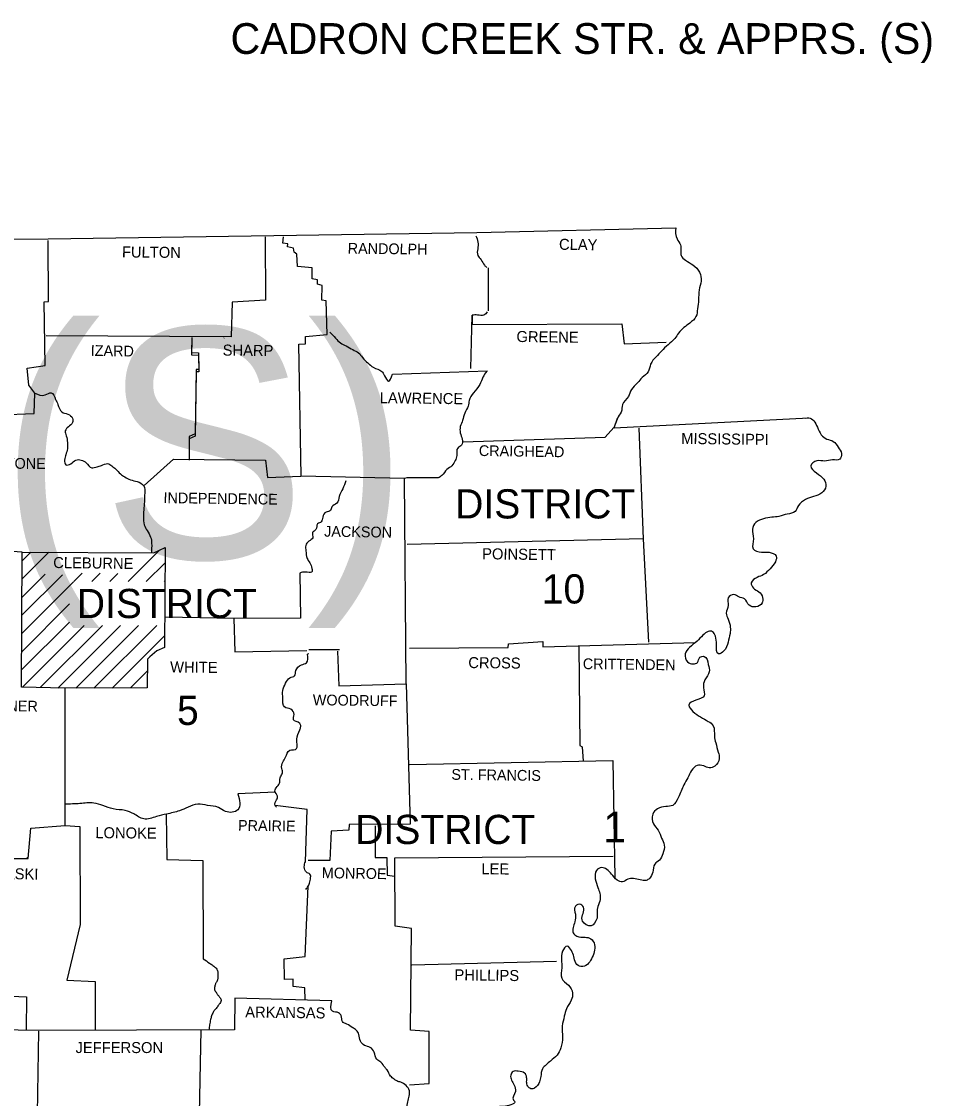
# Model space of a CAD drawing. Extents: x 1212896 to 1368412, y 378476 to 478763.
# Drawn here: x 1348211 to 1365971, y 454801 to 475822 of the extents above; entities that cross this region are included whole.
import ezdxf

# ---------------------------------------------------------------- set-up
doc = ezdxf.new("R2010")
doc.units = 0
doc.layers.add('1', color=7, linetype='Continuous')
doc.layers.add('R_Draft', color=7, linetype='Continuous')

msp = doc.modelspace()

# ---------------------------------------------------------------- linework, layer by layer
at = {"layer": 'R_Draft'}
for p, q in [((1359780, 467892), (1359840, 468077)), ((1359795, 467952), (1359855, 468097)), ((1348222, 464943), (1348743, 465464)), ((1348224, 465298), (1348391, 465466)), ((1350289, 464889), (1350904, 465504)), ((1350643, 464889), (1351012, 465259)), ((1348218, 464232), (1349010, 465024)), ((1348220, 464587), (1348670, 465037)), ((1349229, 464889), (1349397, 465057)), ((1349582, 464889), (1349744, 465051)), ((1349936, 464889), (1350093, 465046)), ((1348216, 463876), (1349227, 464888)), ((1350997, 464889), (1351010, 464902)), ((1348214, 463520), (1349147, 464454)), ((1348212, 463165), (1349147, 464100)), ((1348231, 462831), (1349434, 464034)), ((1348575, 462821), (1349788, 464034)), ((1348918, 462811), (1350142, 464034)), ((1349269, 462808), (1350495, 464034)), ((1349625, 462810), (1350849, 464034)), ((1349980, 462812), (1351002, 463833)), ((1353820, 463562), (1354415, 463562)), ((1350336, 462815), (1350668, 463146))]:
    msp.add_line(p, q, dxfattribs=at)
for points in [[(1333550, 471567), (1341635, 471562), (1348730, 471577), (1357100, 471707), (1360980, 471797)], [(1347215, 459482), (1348340, 459487), (1348390, 460077), (1349060, 460127), (1349060, 462807), (1348210, 462832), (1348225, 465467), (1347155, 465537), (1347140, 466717), (1347105, 466777), (1347135, 467517), (1347755, 467537), (1347780, 468147), (1348460, 468172), (1348470, 468567), (1348350, 468722), (1348320, 469057), (1348670, 469107), (1348655, 470352), (1348740, 470357), (1348730, 471547)], [(1352965, 471622), (1352975, 470382), (1352325, 470347), (1352305, 469667), (1348690, 469687)], [(1354380, 463532), (1354405, 462857), (1355720, 462892), (1355685, 466902), (1353670, 466947), (1353625, 469527), (1353755, 469532), (1353750, 469672), (1354175, 469712), (1354155, 470367), (1354075, 470382), (1354080, 470672), (1353990, 470697), (1353990, 470782), (1353885, 470797), (1353885, 471012), (1353600, 471042), (1353585, 471282), (1353530, 471317), (1353520, 471397), (1353405, 471422), (1353410, 471482), (1353310, 471497), (1353325, 471617)], [(1357320, 471017), (1357320, 470172)], [(1356980, 469047), (1357005, 470092), (1357005, 469907), (1359930, 469922), (1359970, 469532), (1360795, 469562)], [(1351535, 469652), (1351525, 469362), (1351665, 469352), (1351670, 469032), (1351620, 469032), (1351600, 467772), (1351485, 467722), (1351485, 467302)], [(1351535, 469607), (1351525, 469317), (1351665, 469307), (1351670, 468987), (1351620, 468987), (1351600, 467727), (1351485, 467677), (1351485, 467257)], [(1352160, 469642), (1352165, 469647)], [(1355450, 468937), (1357305, 469002)], [(1359780, 467892), (1363575, 468087)], [(1356830, 467617), (1359605, 467707), (1359770, 467897)], [(1360260, 467887), (1360345, 465722), (1360445, 463707)], [(1350605, 466767), (1351175, 467282), (1352975, 467257), (1353010, 466922), (1353665, 466947)], [(1356340, 466912), (1355730, 466912), (1355685, 466902)], [(1360345, 465722), (1355740, 465617)], [(1348225, 465467), (1350795, 465452), (1351015, 465557), (1351000, 463602), (1350850, 463537), (1350715, 463422), (1350670, 463377), (1350665, 462817), (1349060, 462807)], [(1353645, 465057), (1353655, 464177), (1352355, 464172), (1351020, 464197)], [(1352355, 464172), (1352375, 463517), (1353780, 463542)], [(1355780, 463592), (1357710, 463602), (1357715, 463672), (1358385, 463722), (1358385, 463617), (1361363, 463698)], [(1359085, 463636), (1359110, 461692), (1359155, 461662), (1359171, 461385)], [(1353820, 463477), (1353795, 463472)], [(1355720, 462892), (1355795, 460152), (1354605, 460147), (1354600, 460037), (1354255, 460017), (1354225, 459447), (1353805, 459447)], [(1355780, 461317), (1359750, 461397)], [(1359750, 461397), (1359792, 459106)], [(1353160, 460782), (1352435, 460747)], [(1353750, 459422), (1353785, 460442), (1353160, 460522)], [(1351035, 460350), (1351045, 459462), (1351750, 459447), (1351755, 457527)], [(1349060, 460127), (1349350, 460107), (1349355, 458197), (1349095, 457112), (1349650, 457087), (1349645, 456131)], [(1355115, 460122), (1355110, 459502), (1355340, 459502), (1355350, 459157), (1355495, 459142)], [(1348315, 459492), (1348340, 459517)], [(1355780, 455067), (1356170, 455092), (1356165, 456107), (1355800, 456132), (1355820, 458117), (1355505, 458162), (1355495, 459497), (1359760, 459527)], [(1353747, 456720), (1353740, 456962), (1353515, 456987), (1353510, 457127), (1353345, 457122), (1353335, 457527), (1353745, 457572), (1353805, 458942)], [(1345200, 458877), (1345760, 458842), (1345740, 458217), (1346395, 458192), (1346405, 457647), (1346715, 457622), (1346715, 457527), (1347005, 457507), (1347015, 457157), (1347675, 457157), (1347695, 456812), (1348305, 456782), (1348300, 456132)], [(1355830, 457412), (1358650, 457482)], [(1354265, 456707), (1352375, 456757), (1352365, 456142), (1348540, 456127)], [(1348540, 456127), (1347345, 456147), (1347300, 455842), (1346135, 455807), (1346125, 455707), (1345960, 455677), (1345940, 455507), (1345660, 455467)], [(1348540, 456117), (1348510, 454097), (1348395, 454092), (1348380, 452837)], [(1351711, 456139), (1351670, 454177), (1352365, 454122)]]:
    msp.add_lwpolyline(points, dxfattribs=at)
for points in [[(1360980, 471797), (1361005, 471577), (1361075, 471462), (1361085, 471252), (1361170, 471162), (1361315, 471072), (1361445, 470927), (1361475, 470757), (1361435, 470582), (1361425, 470387), (1361405, 470217), (1361375, 470062), (1361255, 469937), (1361140, 469847), (1361035, 469742), (1360960, 469632), (1360830, 469512), (1360700, 469387), (1360595, 469277), (1360490, 469137), (1360440, 468982), (1360325, 468872), (1360235, 468772), (1360115, 468637), (1360055, 468502), (1359940, 468347), (1359915, 468197), (1359840, 468077), (1359835, 468057)], [(1360980, 471797), (1361005, 471577), (1361075, 471462), (1361085, 471252), (1361170, 471162), (1361315, 471072), (1361445, 470927), (1361475, 470757), (1361435, 470582), (1361425, 470387), (1361405, 470217), (1361375, 470062), (1361255, 469937), (1361140, 469847), (1361035, 469742), (1360960, 469632), (1360830, 469512), (1360700, 469387), (1360595, 469277), (1360490, 469137), (1360440, 468982), (1360325, 468872), (1360235, 468772), (1360115, 468637), (1360055, 468502), (1359940, 468347), (1359915, 468197), (1359840, 468077), (1359835, 468057)], [(1357075, 471642), (1357120, 471517), (1357115, 471382), (1357115, 471257), (1357180, 471172), (1357245, 471067), (1357295, 471022)], [(1357300, 470157), (1357235, 470092), (1357110, 470092), (1357005, 470092)], [(1354230, 469757), (1354340, 469642), (1354435, 469547), (1354545, 469492), (1354675, 469417), (1354790, 469357), (1354865, 469262), (1354970, 469157), (1355075, 469072), (1355240, 468992), (1355295, 468907), (1355370, 468802), (1355450, 468937)], [(1357290, 468997), (1357215, 468877), (1357155, 468737), (1357035, 468577), (1356945, 468422), (1356930, 468317), (1356860, 468177), (1356820, 468037), (1356775, 467917), (1356775, 467792), (1356810, 467667), (1356800, 467552), (1356725, 467497), (1356705, 467352), (1356675, 467252), (1356610, 467152), (1356515, 467077), (1356415, 466962), (1356340, 466912)], [(1348470, 468567), (1348670, 468532), (1348790, 468577), (1348875, 468447), (1348920, 468347), (1348995, 468202), (1349115, 468157), (1349205, 468077), (1349205, 467992), (1349125, 467912), (1349065, 467832), (1349085, 467737), (1349105, 467607), (1349105, 467482), (1349075, 467367), (1349050, 467262), (1349075, 467172), (1349170, 467187), (1349270, 467262), (1349375, 467262), (1349475, 467207), (1349580, 467112), (1349685, 467132), (1349770, 467157), (1349890, 467192), (1349975, 467147), (1350050, 467087), (1350140, 466992), (1350225, 466932), (1350335, 466877), (1350470, 466842), (1350595, 466757), (1350615, 466612), (1350610, 466487), (1350600, 466332), (1350590, 466162), (1350605, 465997), (1350660, 465887), (1350730, 465757), (1350750, 465637), (1350745, 465447)], [(1363520, 468082), (1363575, 468087), (1363745, 467907), (1363820, 467757), (1363930, 467672), (1364055, 467627), (1364150, 467512), (1364215, 467387), (1364180, 467277), (1364040, 467267), (1363885, 467242), (1363735, 467247), (1363615, 467147), (1363725, 467012), (1363870, 466887), (1363910, 466752), (1363830, 466622), (1363670, 466552), (1363515, 466492), (1363375, 466372), (1363310, 466257), (1363155, 466207), (1362995, 466162), (1362855, 466147), (1362695, 466117), (1362540, 466042), (1362475, 465912), (1362495, 465727), (1362490, 465532), (1362655, 465467), (1362800, 465462), (1362940, 465387), (1362925, 465277), (1362820, 465137), (1362695, 465027), (1362570, 464972), (1362455, 464867), (1362495, 464762), (1362600, 464692), (1362675, 464577), (1362665, 464472), (1362545, 464397), (1362415, 464427), (1362320, 464552), (1362210, 464592), (1362115, 464637), (1362005, 464572), (1362005, 464427), (1361965, 464272), (1362000, 464157), (1362045, 463997), (1362040, 463877), (1362000, 463707), (1361915, 463532), (1361815, 463477), (1361775, 463667), (1361755, 463822), (1361695, 463912), (1361615, 463917), (1361510, 463842), (1361395, 463727), (1361250, 463602), (1361165, 463477), (1361210, 463322), (1361320, 463282), (1361405, 463312), (1361450, 463412), (1361535, 463427), (1361615, 463272)], [(1363520, 468082), (1363575, 468087), (1363745, 467907), (1363820, 467757), (1363930, 467672), (1364055, 467627), (1364150, 467512), (1364215, 467387), (1364180, 467277), (1364040, 467267), (1363885, 467242), (1363735, 467247), (1363615, 467147), (1363725, 467012), (1363870, 466887), (1363910, 466752), (1363830, 466622), (1363670, 466552), (1363515, 466492), (1363375, 466372), (1363310, 466257), (1363155, 466207), (1362995, 466162), (1362855, 466147), (1362695, 466117), (1362540, 466042), (1362475, 465912), (1362495, 465727), (1362490, 465532), (1362655, 465467), (1362800, 465462), (1362940, 465387), (1362925, 465277), (1362820, 465137), (1362695, 465027), (1362570, 464972), (1362455, 464867), (1362495, 464762), (1362600, 464692), (1362675, 464577), (1362665, 464472), (1362545, 464397), (1362415, 464427), (1362320, 464552), (1362210, 464592), (1362115, 464637), (1362005, 464572), (1362005, 464427), (1361965, 464272), (1362000, 464157), (1362045, 463997), (1362040, 463877), (1362000, 463707), (1361915, 463532), (1361815, 463477), (1361775, 463667), (1361755, 463822), (1361695, 463912), (1361615, 463917), (1361510, 463842), (1361395, 463727), (1361250, 463602), (1361165, 463477), (1361210, 463322), (1361320, 463282), (1361405, 463312), (1361450, 463412), (1361535, 463427), (1361615, 463272)], [(1354540, 466857), (1354480, 466702), (1354410, 466552), (1354365, 466422), (1354270, 466347), (1354240, 466277), (1354155, 466247), (1354090, 466147), (1354060, 466057), (1353990, 466017), (1353955, 465907), (1353890, 465847), (1353895, 465747), (1353820, 465677), (1353760, 465597), (1353760, 465487), (1353785, 465342), (1353835, 465257), (1353880, 465147), (1353875, 465077), (1353750, 465077), (1353645, 465057)], [(1353185, 460487), (1353160, 460522), (1353190, 460632), (1353205, 460702), (1353155, 460802), (1353200, 460887), (1353250, 460977), (1353265, 461082), (1353305, 461152), (1353290, 461242), (1353310, 461367), (1353365, 461462), (1353445, 461597), (1353580, 461632), (1353590, 461687), (1353585, 461812), (1353640, 461997), (1353660, 462062), (1353640, 462122), (1353520, 462192), (1353530, 462297), (1353470, 462397), (1353345, 462442), (1353310, 462612), (1353310, 462762), (1353365, 462907), (1353450, 463012), (1353540, 463052), (1353565, 463152), (1353675, 463262), (1353770, 463307), (1353795, 463472)], [(1361615, 463272), (1361635, 463127), (1361550, 462972), (1361520, 462817), (1361535, 462662), (1361375, 462577), (1361235, 462477), (1361315, 462357), (1361465, 462247), (1361615, 462162), (1361710, 462077), (1361735, 461872), (1361760, 461742), (1361810, 461562), (1361830, 461437), (1361740, 461287), (1361635, 461257), (1361525, 461292), (1361395, 461302), (1361290, 461202), (1361215, 461062), (1361140, 460922), (1361085, 460802), (1361030, 460672), (1360920, 460522), (1360785, 460497), (1360625, 460457), (1360530, 460347), (1360545, 460162), (1360635, 460037), (1360705, 459882), (1360755, 459747), (1360730, 459577), (1360660, 459452), (1360570, 459377), (1360530, 459217), (1360465, 459097), (1360405, 459057), (1360285, 459067), (1360155, 459092), (1360045, 459082), (1359940, 459027), (1359835, 459062), (1359725, 459182), (1359635, 459272), (1359535, 459307), (1359430, 459252), (1359410, 459087), (1359460, 458917), (1359505, 458687), (1359460, 458547), (1359445, 458317)], [(1361615, 463272), (1361635, 463127), (1361550, 462972), (1361520, 462817), (1361535, 462662), (1361375, 462577), (1361235, 462477), (1361315, 462357), (1361465, 462247), (1361615, 462162), (1361710, 462077), (1361735, 461872), (1361760, 461742), (1361810, 461562), (1361830, 461437), (1361740, 461287), (1361635, 461257), (1361525, 461292), (1361395, 461302), (1361290, 461202), (1361215, 461062), (1361140, 460922), (1361085, 460802), (1361030, 460672), (1360920, 460522), (1360785, 460497), (1360625, 460457), (1360530, 460347), (1360545, 460162), (1360635, 460037), (1360705, 459882), (1360755, 459747), (1360730, 459577), (1360660, 459452), (1360570, 459377), (1360530, 459217), (1360465, 459097), (1360405, 459057), (1360285, 459067), (1360155, 459092), (1360045, 459082), (1359940, 459027), (1359835, 459062), (1359725, 459182), (1359635, 459272), (1359535, 459307), (1359430, 459252), (1359410, 459087), (1359460, 458917), (1359505, 458687), (1359460, 458547), (1359445, 458317)], [(1352435, 460747), (1352435, 460437), (1352190, 460402), (1352055, 460482), (1351840, 460522), (1351650, 460547), (1351460, 460487), (1351295, 460417), (1351040, 460352), (1350845, 460302), (1350595, 460257), (1350400, 460357), (1350235, 460422), (1350000, 460452), (1349800, 460517), (1349625, 460567), (1349350, 460557), (1349060, 460546)], [(1353760, 458882), (1353805, 458942), (1353825, 458982), (1353850, 459082), (1353840, 459182), (1353770, 459217), (1353730, 459322), (1353750, 459422)], [(1359445, 458317), (1359330, 458172), (1359160, 458262), (1359160, 458382), (1359185, 458507), (1359125, 458587), (1359020, 458552), (1359020, 458397), (1359010, 458247), (1358980, 458032), (1359050, 457967), (1359210, 457947), (1359325, 457917), (1359395, 457802), (1359390, 457662), (1359335, 457527), (1359255, 457417), (1359130, 457377), (1359030, 457442), (1358990, 457572), (1358945, 457687), (1358860, 457772), (1358770, 457677), (1358750, 457502), (1358755, 457352), (1358755, 457147), (1358885, 457012), (1358965, 456857), (1358940, 456717), (1358845, 456552), (1358805, 456407), (1358765, 456212), (1358770, 455997), (1358735, 455787), (1358665, 455647), (1358535, 455532), (1358450, 455457), (1358380, 455382), (1358345, 455232), (1358320, 455127), (1358225, 455002), (1358150, 454992), (1358090, 455042), (1358070, 455127), (1358070, 455212), (1358030, 455297), (1357905, 455332), (1357805, 455327), (1357760, 455257), (1357825, 455062), (1357850, 454937), (1357815, 454767), (1357835, 454747), (1357655, 454652), (1357510, 454637), (1357390, 454602), (1357275, 454527), (1357220, 454417), (1357140, 454327), (1357070, 454242), (1356975, 454202), (1356870, 454222), (1356730, 454237), (1356650, 454137), (1356675, 453992), (1356770, 453907), (1356910, 453867), (1357055, 453877), (1357195, 453892), (1357325, 453822), (1357300, 453687), (1357175, 453622), (1356990, 453602), (1356840, 453617), (1356660, 453577), (1356570, 453462), (1356620, 453287), (1356815, 453217), (1356905, 453052), (1356910, 452897), (1356845, 452692), (1356755, 452597), (1356580, 452557), (1356445, 452532), (1356425, 452302), (1356365, 452187), (1356260, 452152), (1356110, 452227), (1356020, 452262), (1355910, 452312), (1355770, 452397), (1355665, 452382), (1355695, 452162), (1355705, 452152), (1355825, 451987), (1355945, 451857), (1356000, 451702)], [(1359445, 458317), (1359330, 458172), (1359160, 458262), (1359160, 458382), (1359185, 458507), (1359125, 458587), (1359020, 458552), (1359020, 458397), (1359010, 458247), (1358980, 458032), (1359050, 457967), (1359210, 457947), (1359325, 457917), (1359395, 457802), (1359390, 457662), (1359335, 457527), (1359255, 457417), (1359130, 457377), (1359030, 457442), (1358990, 457572), (1358945, 457687), (1358860, 457772), (1358770, 457677), (1358750, 457502), (1358755, 457352), (1358755, 457147), (1358885, 457012), (1358965, 456857), (1358940, 456717), (1358845, 456552), (1358805, 456407), (1358765, 456212), (1358770, 455997), (1358735, 455787), (1358665, 455647), (1358535, 455532), (1358450, 455457), (1358380, 455382), (1358345, 455232), (1358320, 455127), (1358225, 455002), (1358150, 454992), (1358090, 455042), (1358070, 455127), (1358070, 455212), (1358030, 455297), (1357905, 455332), (1357805, 455327), (1357760, 455257), (1357825, 455062), (1357850, 454937), (1357815, 454767), (1357835, 454747), (1357655, 454652), (1357510, 454637), (1357390, 454602), (1357275, 454527), (1357220, 454417), (1357140, 454327), (1357070, 454242), (1356975, 454202), (1356870, 454222), (1356730, 454237), (1356650, 454137), (1356675, 453992), (1356770, 453907), (1356910, 453867), (1357055, 453877), (1357195, 453892), (1357325, 453822), (1357300, 453687), (1357175, 453622), (1356990, 453602), (1356840, 453617), (1356660, 453577), (1356570, 453462), (1356620, 453287), (1356815, 453217), (1356905, 453052), (1356910, 452897), (1356845, 452692), (1356755, 452597), (1356580, 452557), (1356445, 452532), (1356425, 452302), (1356365, 452187), (1356260, 452152), (1356110, 452227), (1356020, 452262), (1355910, 452312), (1355770, 452397), (1355665, 452382), (1355695, 452162), (1355705, 452152), (1355825, 451987), (1355945, 451857), (1356000, 451702)], [(1351755, 457527), (1351880, 457442), (1351913, 457419), (1351946, 457397), (1351979, 457372), (1351994, 457358), (1352002, 457350), (1352010, 457342), (1352030, 457311), (1352040, 457277), (1352044, 457242), (1352044, 457224), (1352045, 457207), (1352045, 457183), (1352043, 457159), (1352040, 457135), (1352035, 457112), (1352026, 457091), (1352015, 457071), (1352004, 457052), (1351995, 457032), (1351985, 457001), (1351977, 456968), (1351985, 456907), (1351992, 456895), (1351999, 456884), (1352014, 456861), (1352045, 456817), (1352059, 456798), (1352074, 456779), (1352094, 456751), (1352097, 456746), (1352100, 456742), (1352104, 456710), (1352091, 456675), (1352068, 456640), (1352056, 456623), (1352045, 456607), (1352033, 456590), (1352021, 456575), (1351995, 456545), (1351970, 456515), (1351959, 456499), (1351950, 456482), (1351934, 456448), (1351920, 456413), (1351900, 456342), (1351891, 456291), (1351882, 456241), (1351866, 456140)], [(1355535, 453452), (1355600, 453532), (1355645, 453687), (1355665, 453782), (1355680, 453947), (1355685, 454057), (1355735, 454137), (1355760, 454287), (1355715, 454387), (1355725, 454507), (1355735, 454642), (1355755, 454762), (1355780, 454877), (1355780, 454952), (1355715, 455052), (1355615, 455117), (1355535, 455142), (1355485, 455177), (1355415, 455237), (1355345, 455357), (1355305, 455402), (1355225, 455507), (1355145, 455567), (1355095, 455702), (1355015, 455797), (1354905, 455837), (1354825, 455922), (1354795, 456052), (1354745, 456132), (1354675, 456182), (1354560, 456252), (1354475, 456302), (1354450, 456417), (1354400, 456472), (1354280, 456502), (1354265, 456707)]]:
    msp.add_spline(points, degree=3, dxfattribs=at)

# ---------------------------------------------------------------- texts
at = {"layer": '1'}
msp.add_text('CADRON CREEK STR. & APPRS. (S)', height=600, dxfattribs=at).set_placement((1352290, 475190))
at = {"layer": 'R_Draft'}
for s, height, rotation, p in [('RANDOLPH', 210, 359.2583, (1354575, 471292)), ('CLAY', 215, 359.2258, (1358700, 471367)), ('FULTON', 215, 359.4996, (1350170, 471217)), ('GREENE', 215, 359.2361, (1357870, 469567)), ('IZARD', 210, 358.9258, (1349560, 469297)), ('SHARP', 215, 359.3905, (1352135, 469302)), ('LAWRENCE', 215, 359.2678, (1355200, 468372)), ('MISSISSIPPI', 214.98, 359.3097, (1361085, 467577)), ('CRAIGHEAD', 210, 359.1159, (1357135, 467342)), ('STONE', 210, 359.4001, (1347715, 467097)), ('INDEPENDENCE', 209.97, 359.2187, (1350980, 466422)), ('JACKSON', 210, 359.1352, (1354115, 465767)), ('POINSETT', 215, 359.1987, (1357200, 465327)), ('CLEBURNE', 215, 359.2535, (1348828, 465155)), ('WHITE', 215, 359.3139, (1351110, 463117)), ('CROSS', 215, 359.3839, (1356930, 463202)), ('CRITTENDEN', 210, 359.213, (1359165, 463182)), ('WOODRUFF', 210, 359.2748, (1353895, 462477)), ('FAULKNER', 210, 359.2486, (1347030, 462372)), ('ST. FRANCIS', 209.97, 359.2216, (1356600, 461022)), ('PRAIRIE', 210, 359.2116, (1352435, 460027)), ('LONOKE', 215, 359.4974, (1349650, 459882)), ('PULASKI', 215, 359.053, (1347325, 459092)), ('MONROE', 210, 359.0331, (1354070, 459102)), ('LEE', 215, 359.4327, (1357185, 459177)), ('PHILLIPS', 215, 359.3179, (1356660, 457107)), ('ARKANSAS', 215, 359.2678, (1352575, 456382))]:
    msp.add_text(s, height=height, rotation=rotation, dxfattribs=at).set_placement(p)
for s, height, p in [('CADRON CREEK STR. & APPRS. (S)', 4500, (1252802, 465341)), ('DISTRICT', 570, (1356675, 466122)), ('10', 570, (1358365, 464462)), ('DISTRICT', 570, (1349290, 464177)), ('5', 570, (1351245, 462092)), ('1', 600, (1359565, 459802)), ('DISTRICT', 570, (1354725, 459767)), ('JEFFERSON', 215, (1349265, 455687))]:
    msp.add_text(s, height=height, dxfattribs=at).set_placement(p)

doc.saveas('drawing.dxf')
